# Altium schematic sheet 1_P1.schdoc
size 429 x 307 mm; Symbol: Drawing-Symbol_A4; Device: Drawing-Symbol_A4; @Project Name: grandPA2; @Page Count: 1; @Update Date: 2026-07-21; @Create Date: 2026-07-15; @Schematic Name: matrix; @Page No: 1; @Page Name: P1; Company: EasyEDA.com; Version: v0.2; Page Size: A4; @Create Time: 07:05:13; @Update Time: 17:13:13; Width: 1655; Height: 1170; Region Start: 1; X Region Count: 6; Y Region Count: 4; Blade Width: 10; Title Block Position: 3; @Board Name: matrix
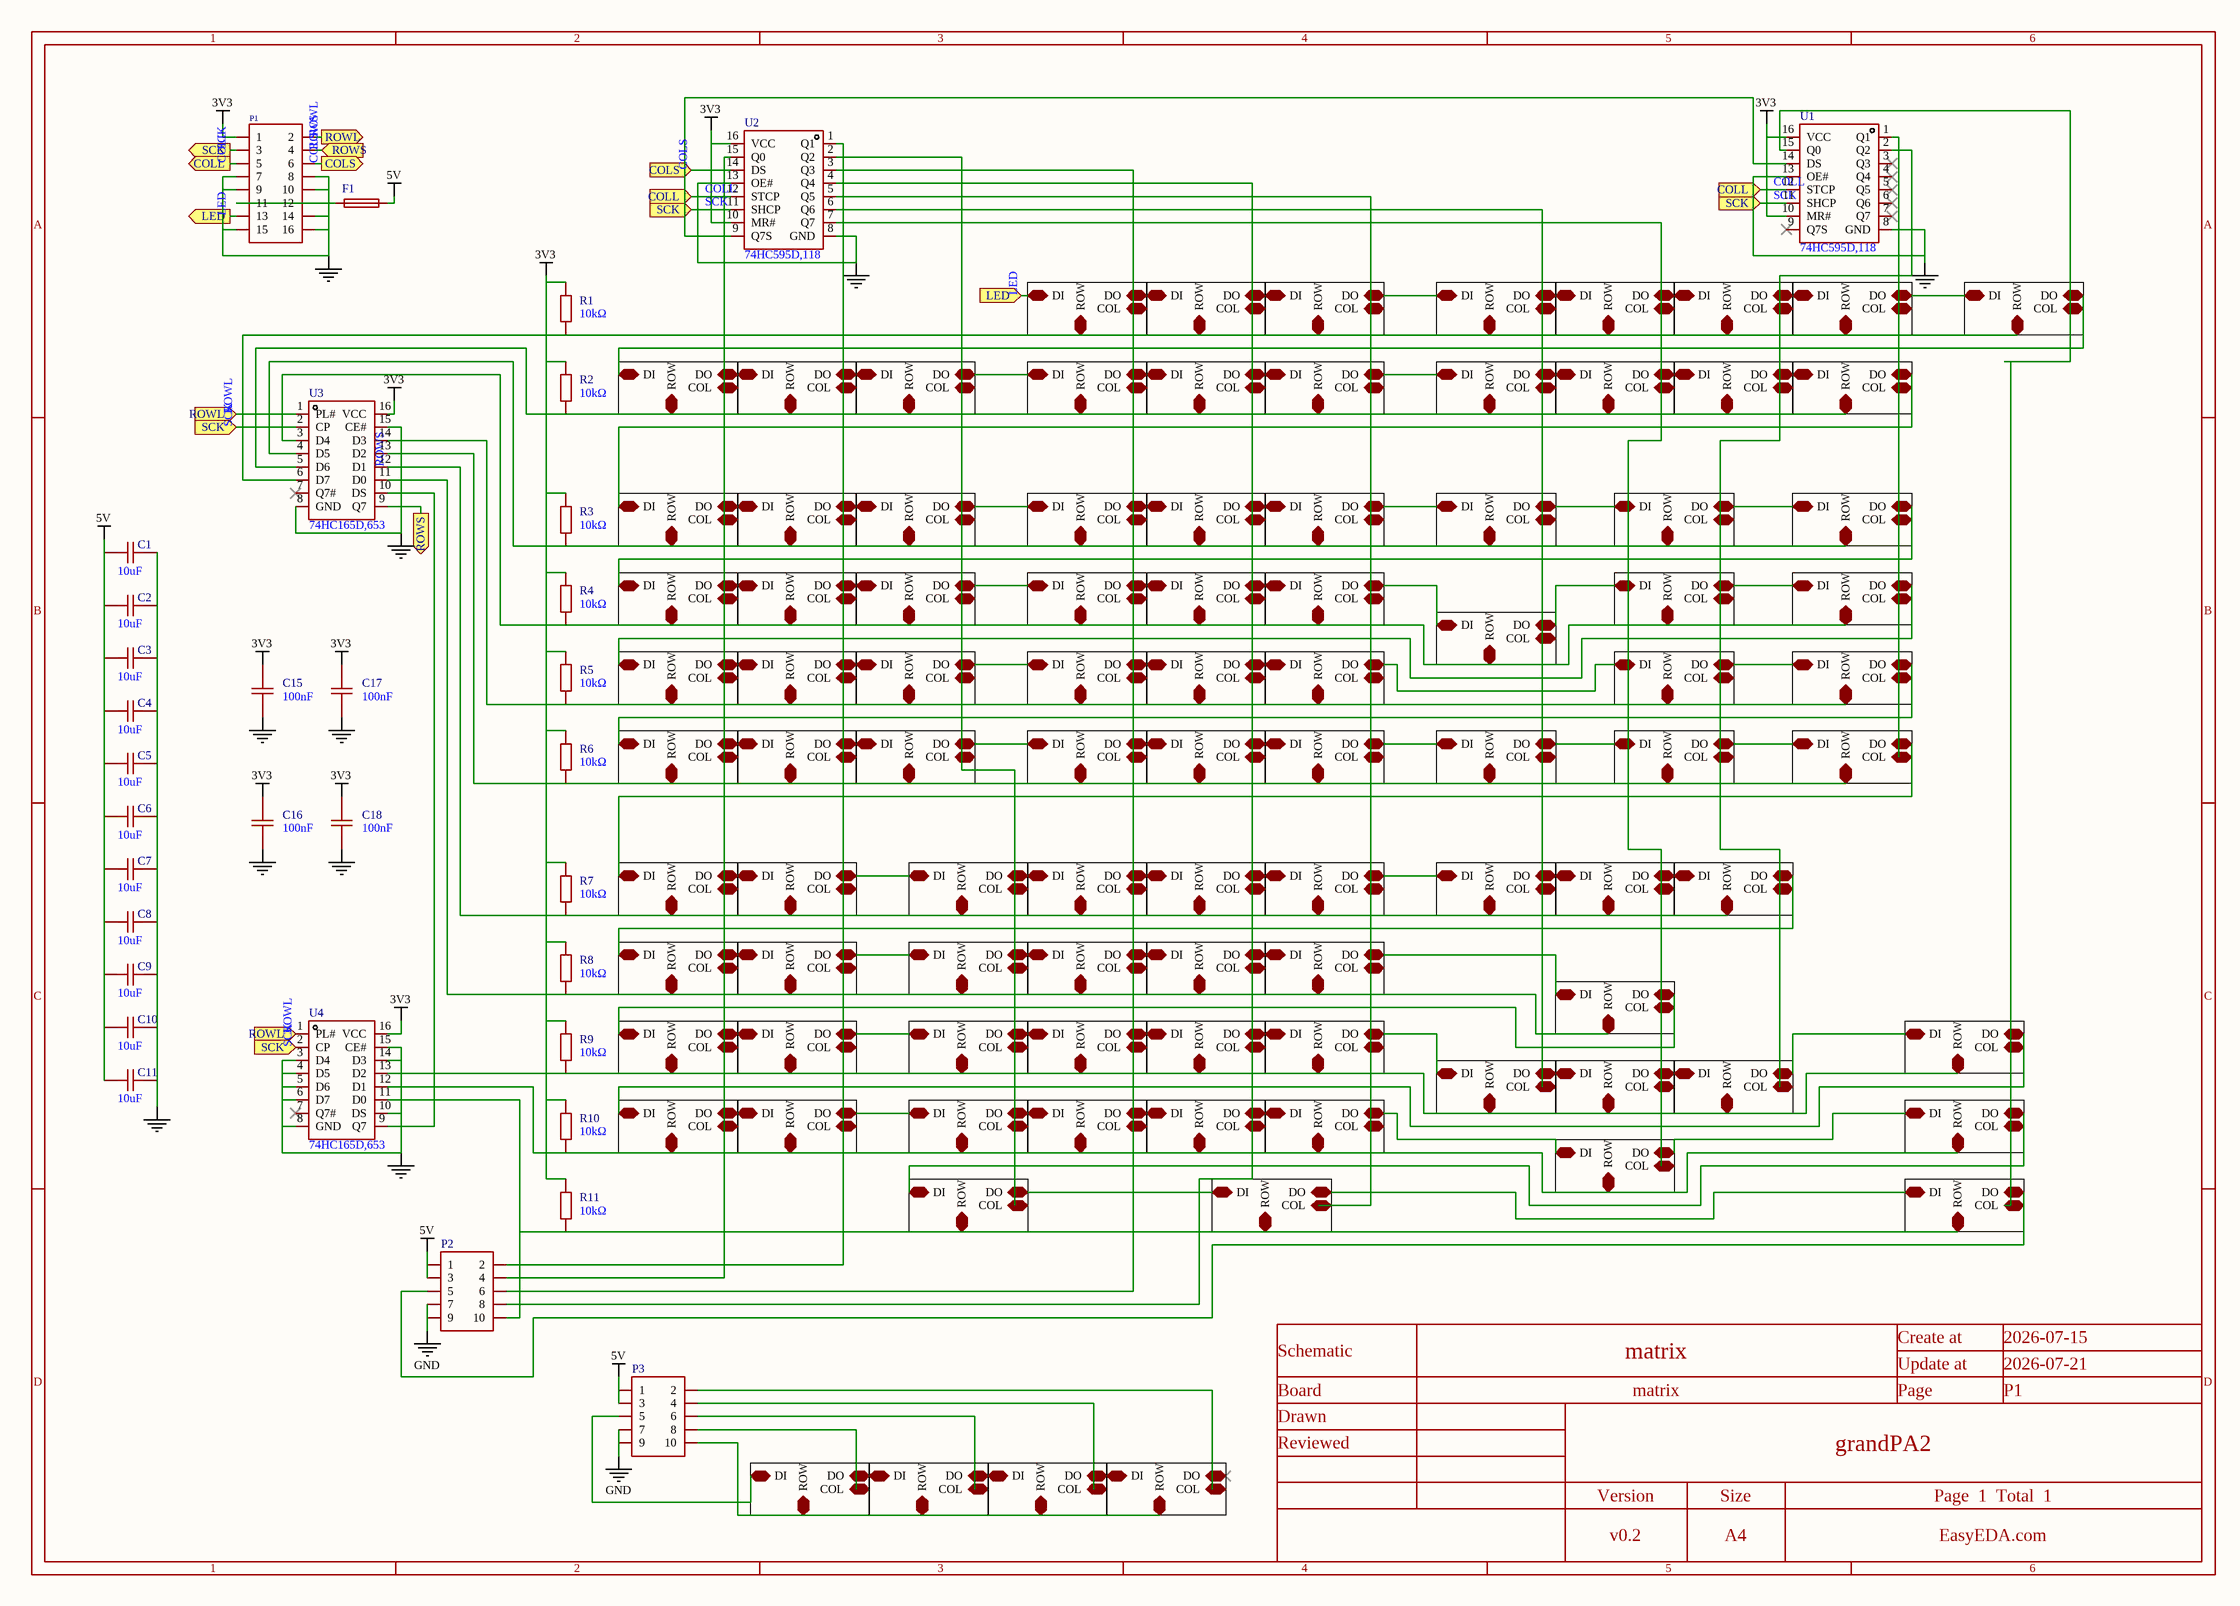
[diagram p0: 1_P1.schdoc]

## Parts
C1  10uF  [C0805]
C2  10uF  [C0805]
C3  10uF  [C0805]
C4  10uF  [C0805]
C5  10uF  [C0805]
C6  10uF  [C0805]
C7  10uF  [C0805]
C8  10uF  [C0805]
C9  10uF  [C0805]
C10  10uF  [C0805]
C11  10uF  [C0805]
C15  100nF  [C0402]
C16  100nF  [C0402]
C17  100nF  [C0402]
C18  100nF  [C0402]
F1  1812L150/24MR  [F1812]  (value not drawn)
P1  2.54-2*8P简牛  [IDC-TH_16P-P2.54_C3406]  (value not drawn)
P2  2.54-2*5P简牛  [IDC-TH_10P-P2.54_C5665]  (value not drawn)
P3  2.54-2*5P简牛  [IDC-TH_10P-P2.54_C5665]  (value not drawn)
R1  10kΩ  [R0402]
R2  10kΩ  [R0402]
R3  10kΩ  [R0402]
R4  10kΩ  [R0402]
R5  10kΩ  [R0402]
R6  10kΩ  [R0402]
R7  10kΩ  [R0402]
R8  10kΩ  [R0402]
R9  10kΩ  [R0402]
R10  10kΩ  [R0402]
R11  10kΩ  [R0402]
U1  74HC595D,118  [SOIC-16_L9.9-W3.9-P1.27-LS6.0-BL]
U2  74HC595D,118  [SOIC-16_L9.9-W3.9-P1.27-LS6.0-BL]
U3  74HC165D,653  [SOIC-16_L9.9-W3.9-P1.27-LS6.0-BL]
U4  74HC165D,653  [SOIC-16_L9.9-W3.9-P1.27-LS6.0-BL]

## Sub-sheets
CBB1 = 1_P1.schdoc: ROW, DI, COL, DO  | Symbol: Key; Device: Key; Relevance: []
CBB2 = 1_P1.schdoc: ROW, DI, COL, DO  | Symbol: Key; Device: Key; Relevance: []
CBB3 = 1_P1.schdoc: ROW, DI, COL, DO  | Symbol: Key; Device: Key; Relevance: []
CBB4 = 1_P1.schdoc: ROW, DI, COL, DO  | Symbol: Key; Device: Key; Relevance: []
CBB5 = 1_P1.schdoc: ROW, DI, COL, DO  | Symbol: Key; Device: Key; Relevance: []
CBB6 = 1_P1.schdoc: ROW, DI, COL, DO  | Symbol: Key; Device: Key; Relevance: []
CBB7 = 1_P1.schdoc: ROW, DI, COL, DO  | Symbol: Key; Device: Key; Relevance: []
CBB8 = 1_P1.schdoc: ROW, DI, COL, DO  | Symbol: Key; Device: Key; Relevance: []
CBB9 = 1_P1.schdoc: ROW, DI, COL, DO  | Symbol: Key; Device: Key; Relevance: []
CBB10 = 1_P1.schdoc: ROW, DI, COL, DO  | Symbol: Key; Device: Key; Relevance: []
CBB11 = 1_P1.schdoc: ROW, DI, COL, DO  | Symbol: Key; Device: Key; Relevance: []
CBB12 = 1_P1.schdoc: ROW, DI, COL, DO  | Symbol: Key; Device: Key; Relevance: []
CBB13 = 1_P1.schdoc: ROW, DI, COL, DO  | Symbol: Key; Device: Key; Relevance: []
CBB14 = 1_P1.schdoc: ROW, DI, COL, DO  | Symbol: Key; Device: Key; Relevance: []
CBB15 = 1_P1.schdoc: ROW, DI, COL, DO  | Symbol: Key; Device: Key; Relevance: []
CBB16 = 1_P1.schdoc: ROW, DI, COL, DO  | Symbol: Key; Device: Key; Relevance: []
CBB17 = 1_P1.schdoc: ROW, DI, COL, DO  | Symbol: Key; Device: Key; Relevance: []
CBB18 = 1_P1.schdoc: ROW, DI, COL, DO  | Symbol: Key; Device: Key; Relevance: []
CBB19 = 1_P1.schdoc: ROW, DI, COL, DO  | Symbol: Key; Device: Key; Relevance: []
CBB20 = 1_P1.schdoc: ROW, DI, COL, DO  | Symbol: Key; Device: Key; Relevance: []
CBB21 = 1_P1.schdoc: ROW, DI, COL, DO  | Symbol: Key; Device: Key; Relevance: []
CBB22 = 1_P1.schdoc: ROW, DI, COL, DO  | Symbol: Key; Device: Key; Relevance: []
CBB23 = 1_P1.schdoc: ROW, DI, COL, DO  | Symbol: Key; Device: Key; Relevance: []
CBB24 = 1_P1.schdoc: ROW, DI, COL, DO  | Symbol: Key; Device: Key; Relevance: []
CBB25 = 1_P1.schdoc: ROW, DI, COL, DO  | Symbol: Key; Device: Key; Relevance: []
CBB26 = 1_P1.schdoc: ROW, DI, COL, DO  | Symbol: Key; Device: Key; Relevance: []
CBB27 = 1_P1.schdoc: ROW, DI, COL, DO  | Symbol: Key; Device: Key; Relevance: []
CBB28 = 1_P1.schdoc: ROW, DI, COL, DO  | Symbol: Key; Device: Key; Relevance: []
CBB29 = 1_P1.schdoc: ROW, DI, COL, DO  | Symbol: Key; Device: Key; Relevance: []
CBB30 = 1_P1.schdoc: ROW, DI, COL, DO  | Symbol: Key; Device: Key; Relevance: []
CBB31 = 1_P1.schdoc: ROW, DI, COL, DO  | Symbol: Key; Device: Key; Relevance: []
CBB32 = 1_P1.schdoc: ROW, DI, COL, DO  | Symbol: Key; Device: Key; Relevance: []
CBB33 = 1_P1.schdoc: ROW, DI, COL, DO  | Symbol: Key; Device: Key; Relevance: []
CBB34 = 1_P1.schdoc: ROW, DI, COL, DO  | Symbol: Key; Device: Key; Relevance: []
CBB35 = 1_P1.schdoc: ROW, DI, COL, DO  | Symbol: Key; Device: Key; Relevance: []
CBB36 = 1_P1.schdoc: ROW, DI, COL, DO  | Symbol: Key; Device: Key; Relevance: []
CBB37 = 1_P1.schdoc: ROW, DI, COL, DO  | Symbol: Key; Device: Key; Relevance: []
CBB38 = 1_P1.schdoc: ROW, DI, COL, DO  | Symbol: Key; Device: Key; Relevance: []
CBB39 = 1_P1.schdoc: ROW, DI, COL, DO  | Symbol: Key; Device: Key; Relevance: []
CBB40 = 1_P1.schdoc: ROW, DI, COL, DO  | Symbol: Key; Device: Key; Relevance: []
CBB41 = 1_P1.schdoc: ROW, DI, COL, DO  | Symbol: Key; Device: Key; Relevance: []
CBB42 = 1_P1.schdoc: ROW, DI, COL, DO  | Symbol: Key; Device: Key; Relevance: []
CBB43 = 1_P1.schdoc: ROW, DI, COL, DO  | Symbol: Key; Device: Key; Relevance: []
CBB44 = 1_P1.schdoc: ROW, DI, COL, DO  | Symbol: Key; Device: Key; Relevance: []
CBB45 = 1_P1.schdoc: ROW, DI, COL, DO  | Symbol: Key; Device: Key; Relevance: []
CBB46 = 1_P1.schdoc: ROW, DI, COL, DO  | Symbol: Key; Device: Key; Relevance: []
CBB47 = 1_P1.schdoc: ROW, DI, COL, DO  | Symbol: Key; Device: Key; Relevance: []
CBB48 = 1_P1.schdoc: ROW, DI, COL, DO  | Symbol: Key; Device: Key; Relevance: []
CBB49 = 1_P1.schdoc: ROW, DI, COL, DO  | Symbol: Key; Device: Key; Relevance: []
CBB50 = 1_P1.schdoc: ROW, DI, COL, DO  | Symbol: Key; Device: Key; Relevance: []
CBB51 = 1_P1.schdoc: ROW, DI, COL, DO  | Symbol: Key; Device: Key; Relevance: []
CBB52 = 1_P1.schdoc: ROW, DI, COL, DO  | Symbol: Key; Device: Key; Relevance: []
CBB53 = 1_P1.schdoc: ROW, DI, COL, DO  | Symbol: Key; Device: Key; Relevance: []
CBB54 = 1_P1.schdoc: ROW, DI, COL, DO  | Symbol: Key; Device: Key; Relevance: []
CBB55 = 1_P1.schdoc: ROW, DI, COL, DO  | Symbol: Key; Device: Key; Relevance: []
CBB56 = 1_P1.schdoc: ROW, DI, COL, DO  | Symbol: Key; Device: Key; Relevance: []
CBB57 = 1_P1.schdoc: ROW, DI, COL, DO  | Symbol: Key; Device: Key; Relevance: []
CBB58 = 1_P1.schdoc: ROW, DI, COL, DO  | Symbol: Key; Device: Key; Relevance: []
CBB59 = 1_P1.schdoc: ROW, DI, COL, DO  | Symbol: Key; Device: Key; Relevance: []
CBB60 = 1_P1.schdoc: ROW, DI, COL, DO  | Symbol: Key; Device: Key; Relevance: []
CBB61 = 1_P1.schdoc: ROW, DI, COL, DO  | Symbol: Key; Device: Key; Relevance: []
CBB62 = 1_P1.schdoc: ROW, DI, COL, DO  | Symbol: Key; Device: Key; Relevance: []
CBB63 = 1_P1.schdoc: ROW, DI, COL, DO  | Symbol: Key; Device: Key; Relevance: []
CBB64 = 1_P1.schdoc: ROW, DI, COL, DO  | Symbol: Key; Device: Key; Relevance: []
CBB65 = 1_P1.schdoc: ROW, DI, COL, DO  | Symbol: Key; Device: Key; Relevance: []
CBB66 = 1_P1.schdoc: ROW, DI, COL, DO  | Symbol: Key; Device: Key; Relevance: []
CBB67 = 1_P1.schdoc: ROW, DI, COL, DO  | Symbol: Key; Device: Key; Relevance: []
CBB68 = 1_P1.schdoc: ROW, DI, COL, DO  | Symbol: Key; Device: Key; Relevance: []
CBB69 = 1_P1.schdoc: ROW, DI, COL, DO  | Symbol: Key; Device: Key; Relevance: []
CBB70 = 1_P1.schdoc: ROW, DI, COL, DO  | Symbol: Key; Device: Key; Relevance: []
CBB71 = 1_P1.schdoc: ROW, DI, COL, DO  | Symbol: Key; Device: Key; Relevance: []
CBB72 = 1_P1.schdoc: ROW, DI, COL, DO  | Symbol: Key; Device: Key; Relevance: []
CBB73 = 1_P1.schdoc: ROW, DI, COL, DO  | Symbol: Key; Device: Key; Relevance: []
CBB74 = 1_P1.schdoc: ROW, DI, COL, DO  | Symbol: Key; Device: Key; Relevance: []
CBB75 = 1_P1.schdoc: ROW, DI, COL, DO  | Symbol: Key; Device: Key; Relevance: []
CBB76 = 1_P1.schdoc: ROW, DI, COL, DO  | Symbol: Key; Device: Key; Relevance: []
CBB77 = 1_P1.schdoc: ROW, DI, COL, DO  | Symbol: Key; Device: Key; Relevance: []
CBB78 = 1_P1.schdoc: ROW, DI, COL, DO  | Symbol: Key; Device: Key; Relevance: []
CBB79 = 1_P1.schdoc: ROW, DI, COL, DO  | Symbol: Key; Device: Key; Relevance: []
CBB80 = 1_P1.schdoc: ROW, DI, COL, DO  | Symbol: Key; Device: Key; Relevance: []
CBB81 = 1_P1.schdoc: ROW, DI, COL, DO  | Symbol: Key; Device: Key; Relevance: []
CBB82 = 1_P1.schdoc: ROW, DI, COL, DO  | Symbol: Key; Device: Key; Relevance: []
CBB83 = 1_P1.schdoc: ROW, DI, COL, DO  | Symbol: Key; Device: Key; Relevance: []
CBB84 = 1_P1.schdoc: ROW, DI, COL, DO  | Symbol: Key; Device: Key; Relevance: []
CBB85 = 1_P1.schdoc: ROW, DI, COL, DO  | Symbol: Key; Device: Key; Relevance: []
CBB86 = 1_P1.schdoc: ROW, DI, COL, DO  | Symbol: Key; Device: Key; Relevance: []
CBB87 = 1_P1.schdoc: ROW, DI, COL, DO  | Symbol: Key; Device: Key; Relevance: []
KEY1 = 1_P1.schdoc: ROW, DI, COL, DO  | Symbol: Key; Device: Key; Relevance: []
KEY2 = 1_P1.schdoc: ROW, DI, COL, DO  | Symbol: Key; Device: Key; Relevance: []
KEY3 = 1_P1.schdoc: ROW, DI, COL, DO  | Symbol: Key; Device: Key; Relevance: []
KEY4 = 1_P1.schdoc: ROW, DI, COL, DO  | Symbol: Key; Device: Key; Relevance: []
KEY5 = 1_P1.schdoc: ROW, DI, COL, DO  | Symbol: Key; Device: Key; Relevance: []
KEY6 = 1_P1.schdoc: ROW, DI, COL, DO  | Symbol: Key; Device: Key; Relevance: []
KEY7 = 1_P1.schdoc: ROW, DI, COL, DO  | Symbol: Key; Device: Key; Relevance: []

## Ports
COLL (in), COLL (out), COLS (in), COLS (out), LED (in), LED (out), ROWL (in), ROWL (out), ROWS (in), ROWS (out), SCK (in), SCK (out)

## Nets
3V3: C15.2 C16.2 C17.2 C18.2 P1.1 R1.2 R2.2 R3.2 R4.2 R5.2 R6.2 R7.2 R8.2 R9.2 R10.2 R11.2 U1.10(MR#) U1.16(VCC) U2.10(MR#) U2.16(VCC) U3.16(VCC) U4.16(VCC)
5V: C1.2 C2.2 C3.1 C4.2 C5.2 C6.2 C7.2 C8.2 C9.2 C10.2 C11.2 F1.2 P2.1 P2.3 P3.1 P3.3
GND: C1.1 C2.1 C3.2 C4.1 C5.1 C6.1 C7.1 C8.1 C9.1 C10.1 C11.1 C15.1 C16.1 C17.1 C18.1 P1.7 P1.8 P1.9 P1.10 P1.14 P1.15 P1.16 P2.7 P2.9 P3.7 P3.9 U1.8(GND) U1.13(OE#) U2.8(GND) U2.13(OE#) U3.8(GND) U3.15(CE#) U4.3(D4) U4.4(D5) U4.5(D6) U4.6(D7) U4.8(GND) U4.10(DS) U4.14(D3) U4.15(CE#)
COLL: P1.5 U1.12(STCP) U2.12(STCP) ; port COLL
COLS: P1.6 U2.14(DS) ; port COLS
LED: P1.13 ; port LED, sheet KEY7/DI
ROWL: P1.2 U3.1(PL#) U4.1(PL#) ; port ROWL
ROWS: P1.4 R7.1 U3.9(Q7) U3.12(D1) ; port ROWS, sheet CBB36/ROW, sheet CBB37/ROW, sheet CBB38/ROW, sheet CBB39/ROW, sheet CBB40/ROW, sheet CBB41/ROW, sheet CBB71/ROW, sheet CBB72/ROW, sheet CBB73/ROW
SCK: P1.3 U1.11(SHCP) U2.11(SHCP) U3.2(CP) U4.2(CP) ; port SCK
NetF1_1: F1.1 P1.11 P1.12
NetP2_2: P2.2 U2.1(Q1)
NetP2_4: P2.4 U2.15(Q0)
NetP2_5: P2.5 ; sheet CBB87/COL, sheet CBB87/DO
NetP2_6: P2.6 U2.3(Q3)
NetP2_8: P2.8 U2.4(Q4)
NetP2_10: P2.10 R11.1 U4.11(D0) ; sheet CBB79/ROW, sheet CBB84/ROW, sheet CBB87/ROW
NetP3_5: P3.5 ; sheet CBB80/DI
NetP3_10: P3.10 ; sheet CBB80/ROW, sheet CBB81/ROW, sheet CBB82/ROW, sheet CBB83/ROW
NetR1_1: R1.1 U3.6(D7) ; sheet CBB1/ROW, sheet KEY1/ROW, sheet KEY2/ROW, sheet KEY3/ROW, sheet KEY4/ROW, sheet KEY5/ROW, sheet KEY6/ROW, sheet KEY7/ROW
NetR2_1: R2.1 U3.5(D6) ; sheet CBB2/ROW, sheet CBB3/ROW, sheet CBB4/ROW, sheet CBB5/ROW, sheet CBB6/ROW, sheet CBB7/ROW, sheet CBB8/ROW, sheet CBB9/ROW, sheet CBB10/ROW, sheet CBB11/ROW
NetR3_1: R3.1 U3.4(D5) ; sheet CBB12/ROW, sheet CBB13/ROW, sheet CBB14/ROW, sheet CBB15/ROW, sheet CBB16/ROW, sheet CBB17/ROW, sheet CBB60/ROW, sheet CBB65/ROW, sheet CBB68/ROW
NetR4_1: R4.1 U3.3(D4) ; sheet CBB18/ROW, sheet CBB19/ROW, sheet CBB20/ROW, sheet CBB21/ROW, sheet CBB22/ROW, sheet CBB23/ROW, sheet CBB61/ROW, sheet CBB64/ROW, sheet CBB69/ROW
NetR5_1: R5.1 U3.14(D3) ; sheet CBB24/ROW, sheet CBB25/ROW, sheet CBB26/ROW, sheet CBB27/ROW, sheet CBB28/ROW, sheet CBB29/ROW, sheet CBB62/ROW, sheet CBB67/ROW
NetR6_1: R6.1 U3.13(D2) ; sheet CBB30/ROW, sheet CBB31/ROW, sheet CBB32/ROW, sheet CBB33/ROW, sheet CBB34/ROW, sheet CBB35/ROW, sheet CBB63/ROW, sheet CBB66/ROW, sheet CBB70/ROW
NetR8_1: R8.1 U3.11(D0) ; sheet CBB42/ROW, sheet CBB43/ROW, sheet CBB44/ROW, sheet CBB45/ROW, sheet CBB46/ROW, sheet CBB47/ROW, sheet CBB77/ROW
NetR9_1: R9.1 U4.13(D2) ; sheet CBB48/ROW, sheet CBB49/ROW, sheet CBB50/ROW, sheet CBB51/ROW, sheet CBB52/ROW, sheet CBB53/ROW, sheet CBB74/ROW, sheet CBB75/ROW, sheet CBB76/ROW, sheet CBB86/ROW
NetR10_1: R10.1 U4.12(D1) ; sheet CBB54/ROW, sheet CBB55/ROW, sheet CBB56/ROW, sheet CBB57/ROW, sheet CBB58/ROW, sheet CBB59/ROW, sheet CBB78/ROW, sheet CBB85/ROW
NetU1_14: U1.14(DS) U2.9(Q7S)
NetU2_5: U2.5(Q5) ; sheet CBB84/COL
NetU3_10: U3.10(DS) U4.9(Q7)
(unnamed): sheet CBB1/DI, sheet KEY1/DO
(unnamed): sheet CBB1/COL, sheet CBB1/DO, sheet CBB11/DI  [a separate net that carries the same name]
(unnamed): sheet KEY1/DI, sheet KEY2/DO  [a separate net that carries the same name]
(unnamed): sheet CBB2/DI, sheet CBB3/DO  [a separate net that carries the same name]
(unnamed): sheet CBB2/COL, sheet CBB2/DO, sheet CBB17/DI  [a separate net that carries the same name]
(unnamed): sheet KEY2/DI, sheet KEY3/DO  [a separate net that carries the same name]
(unnamed): sheet CBB3/DI, sheet CBB4/DO  [a separate net that carries the same name]
(unnamed): sheet KEY3/DI, sheet KEY4/DO  [a separate net that carries the same name]
(unnamed): sheet CBB4/DI, sheet CBB5/DO  [a separate net that carries the same name]
(unnamed): sheet KEY4/DI, sheet KEY5/DO  [a separate net that carries the same name]
(unnamed): sheet CBB5/DI, sheet CBB6/DO  [a separate net that carries the same name]
(unnamed): sheet KEY5/DI, sheet KEY6/DO  [a separate net that carries the same name]
(unnamed): sheet CBB6/DI, sheet CBB7/DO  [a separate net that carries the same name]
(unnamed): sheet KEY6/DI, sheet KEY7/DO  [a separate net that carries the same name]
(unnamed): sheet CBB7/DI, sheet CBB8/DO  [a separate net that carries the same name]
(unnamed): sheet CBB8/DI, sheet CBB9/DO  [a separate net that carries the same name]
(unnamed): sheet CBB9/DI, sheet CBB10/DO  [a separate net that carries the same name]
(unnamed): sheet CBB10/DI, sheet CBB11/DO  [a separate net that carries the same name]
(unnamed): sheet CBB12/DI, sheet CBB13/DO  [a separate net that carries the same name]
(unnamed): sheet CBB12/DO, sheet CBB68/DI  [a separate net that carries the same name]
(unnamed): sheet CBB13/DI, sheet CBB14/DO  [a separate net that carries the same name]
(unnamed): sheet CBB14/DI, sheet CBB15/DO  [a separate net that carries the same name]
(unnamed): sheet CBB15/DI, sheet CBB16/DO  [a separate net that carries the same name]
(unnamed): sheet CBB16/DI, sheet CBB17/DO  [a separate net that carries the same name]
(unnamed): sheet CBB18/DI, sheet CBB19/DO  [a separate net that carries the same name]
(unnamed): sheet CBB18/DO, sheet CBB69/DI  [a separate net that carries the same name]
(unnamed): sheet CBB19/DI, sheet CBB20/DO  [a separate net that carries the same name]
(unnamed): sheet CBB20/DI, sheet CBB21/DO  [a separate net that carries the same name]
(unnamed): sheet CBB21/DI, sheet CBB22/DO  [a separate net that carries the same name]
(unnamed): sheet CBB22/DI, sheet CBB23/DO  [a separate net that carries the same name]
(unnamed): sheet CBB23/DI, sheet CBB60/COL, sheet CBB60/DO  [a separate net that carries the same name]
(unnamed): sheet CBB24/DI, sheet CBB25/DO  [a separate net that carries the same name]
(unnamed): sheet CBB24/DO, sheet CBB67/DI  [a separate net that carries the same name]
(unnamed): sheet CBB25/DI, sheet CBB26/DO  [a separate net that carries the same name]
(unnamed): sheet CBB26/DI, sheet CBB27/DO  [a separate net that carries the same name]
(unnamed): sheet CBB27/DI, sheet CBB28/DO  [a separate net that carries the same name]
(unnamed): sheet CBB28/DI, sheet CBB29/DO  [a separate net that carries the same name]
(unnamed): sheet CBB29/DI, sheet CBB61/COL, sheet CBB61/DO  [a separate net that carries the same name]
(unnamed): sheet CBB30/DI, sheet CBB31/DO  [a separate net that carries the same name]
(unnamed): sheet CBB30/DO, sheet CBB70/DI  [a separate net that carries the same name]
(unnamed): sheet CBB31/DI, sheet CBB32/DO  [a separate net that carries the same name]
(unnamed): sheet CBB32/DI, sheet CBB33/DO  [a separate net that carries the same name]
(unnamed): sheet CBB33/DI, sheet CBB34/DO  [a separate net that carries the same name]
(unnamed): sheet CBB34/DI, sheet CBB35/DO  [a separate net that carries the same name]
(unnamed): sheet CBB35/DI, sheet CBB62/COL, sheet CBB62/DO  [a separate net that carries the same name]
(unnamed): sheet CBB36/DI, sheet CBB37/DO  [a separate net that carries the same name]
(unnamed): sheet CBB36/DO, sheet CBB71/DI  [a separate net that carries the same name]
(unnamed): sheet CBB37/DI, sheet CBB38/DO  [a separate net that carries the same name]
(unnamed): sheet CBB38/DI, sheet CBB39/DO  [a separate net that carries the same name]
(unnamed): sheet CBB39/DI, sheet CBB40/DO  [a separate net that carries the same name]
(unnamed): sheet CBB40/DI, sheet CBB41/DO  [a separate net that carries the same name]
(unnamed): sheet CBB41/DI, sheet CBB63/COL, sheet CBB63/DO  [a separate net that carries the same name]
(unnamed): sheet CBB42/DI, sheet CBB43/DO  [a separate net that carries the same name]
(unnamed): sheet CBB42/DO, sheet CBB77/DI  [a separate net that carries the same name]
(unnamed): sheet CBB43/DI, sheet CBB44/DO  [a separate net that carries the same name]
(unnamed): sheet CBB44/DI, sheet CBB45/DO  [a separate net that carries the same name]
(unnamed): sheet CBB45/DI, sheet CBB46/DO  [a separate net that carries the same name]
(unnamed): sheet CBB46/DI, sheet CBB47/DO  [a separate net that carries the same name]
(unnamed): sheet CBB47/DI, sheet CBB73/COL, sheet CBB73/DO  [a separate net that carries the same name]
(unnamed): sheet CBB48/DI, sheet CBB49/DO  [a separate net that carries the same name]
(unnamed): sheet CBB48/DO, sheet CBB74/DI  [a separate net that carries the same name]
(unnamed): sheet CBB49/DI, sheet CBB50/DO  [a separate net that carries the same name]
(unnamed): sheet CBB50/DI, sheet CBB51/DO  [a separate net that carries the same name]
(unnamed): sheet CBB51/DI, sheet CBB52/DO  [a separate net that carries the same name]
(unnamed): sheet CBB52/DI, sheet CBB53/DO  [a separate net that carries the same name]
(unnamed): sheet CBB53/DI, sheet CBB77/COL, sheet CBB77/DO  [a separate net that carries the same name]
(unnamed): sheet CBB54/DI, sheet CBB55/DO  [a separate net that carries the same name]
(unnamed): sheet CBB54/DO, sheet CBB78/DI  [a separate net that carries the same name]
(unnamed): sheet CBB55/DI, sheet CBB56/DO  [a separate net that carries the same name]
(unnamed): sheet CBB56/DI, sheet CBB57/DO  [a separate net that carries the same name]
(unnamed): sheet CBB57/DI, sheet CBB58/DO  [a separate net that carries the same name]
(unnamed): sheet CBB58/DI, sheet CBB59/DO  [a separate net that carries the same name]
(unnamed): sheet CBB59/DI, sheet CBB86/COL, sheet CBB86/DO  [a separate net that carries the same name]
(unnamed): sheet CBB60/DI, sheet CBB65/DO  [a separate net that carries the same name]
(unnamed): sheet CBB61/DI, sheet CBB64/DO  [a separate net that carries the same name]
(unnamed): sheet CBB62/DI, sheet CBB67/DO  [a separate net that carries the same name]
(unnamed): sheet CBB63/DI, sheet CBB66/DO  [a separate net that carries the same name]
(unnamed): sheet CBB65/DI, sheet CBB68/DO  [a separate net that carries the same name]
(unnamed): sheet CBB64/DI, sheet CBB69/DO  [a separate net that carries the same name]
(unnamed): sheet CBB66/DI, sheet CBB70/DO  [a separate net that carries the same name]
(unnamed): sheet CBB71/DO, sheet CBB72/DI  [a separate net that carries the same name]
(unnamed): sheet CBB72/DO, sheet CBB73/DI  [a separate net that carries the same name]
(unnamed): sheet CBB74/DO, sheet CBB75/DI  [a separate net that carries the same name]
(unnamed): sheet CBB75/DO, sheet CBB76/DI  [a separate net that carries the same name]
(unnamed): sheet CBB76/DO, sheet CBB86/DI  [a separate net that carries the same name]
(unnamed): sheet CBB78/DO, sheet CBB85/DI  [a separate net that carries the same name]
(unnamed): sheet CBB79/DI, sheet CBB85/COL, sheet CBB85/DO  [a separate net that carries the same name]
(unnamed): sheet CBB79/DO, sheet CBB84/DI  [a separate net that carries the same name]
(unnamed): sheet CBB80/DO, sheet CBB81/DI  [a separate net that carries the same name]
(unnamed): sheet CBB81/DO, sheet CBB82/DI  [a separate net that carries the same name]
(unnamed): sheet CBB82/DO, sheet CBB83/DI  [a separate net that carries the same name]
(unnamed): sheet CBB84/DO, sheet CBB87/DI  [a separate net that carries the same name]

Not connected (* = marked no-connect by the designer): P3 2 4 6 8; U1 1(Q1) 2(Q2) 3(Q3)* 4(Q4)* 5(Q5)* 6(Q6)* 7(Q7)* 9(Q7S)* 15(Q0); U2 2(Q2) 6(Q6) 7(Q7); U3 7(Q7#)*; U4 7(Q7#)*

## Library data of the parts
C1-C11 = CL21A106KAYNNNE_C15850: Manufacturer: SAMSUNG(三星); Add into BOM: yes; Tolerance: ±10%; Voltage Rating: 25V; Temperature Coefficient: X5R
C15-C18 = CL05B104KO5NNNC: Manufacturer: SAMSUNG(三星); Add into BOM: yes; Tolerance: ±10%; Voltage Rating: 16V; Temperature Coefficient: X7R
F1 = 1812L150/24MR: Manufacturer: Littelfuse(美国力特); Add into BOM: yes; Voltage - Max: 24V; Current - Max: 20A; Hold Current: 1.5A; Trip Current: 3A; Power Dissipation: 800mW; Resistance - Initial (Ri) (Min): 40mΩ; Resistance - Post Trip (R1) (Max): 120mΩ; Time to Trip(Max): 1.5s
P1 = 2.54-2*8P简牛: Manufacturer: BOOMELE(博穆精密); Symbol: HDR-IDC-2.54-2X8P; Add into BOM: yes; Connector Type: IDC Header; Pitch: 2.54mm; Number of Positions or Pins: 2x8P; Current Rating: 1A; Holder Type: Through Hole; Number of PINs Per Row: 8
P2 P3 = 2.54-2*5P简牛: Manufacturer: BOOMELE(博穆精密); Symbol: HDR-IDC-2.54-2X5P; Add into BOM: yes; Connector Type: IDC Header; Pitch: 2.54mm; Number of Positions or Pins: 2x5P; Current Rating: 1A; Holder Type: Through Hole; Number of PINs Per Row: 5
R1-R11 = 0402WGF1002TCE: Manufacturer: UNI-ROYAL(厚声); Add into BOM: yes; Tolerance: ±1%; Power(Watts): 62.5mW; Voltage-Supply(Max): 50V; Temperature Coefficient: ±100ppm/℃
U1 U2 = 74HC595D,118: Manufacturer: Nexperia(安世); Add into BOM: yes; Function: Serial-to-Serial or Parallel; Voltage - Supply: 2V~6V; Clock Frequency: 100MHz; Number of Elements: 1; Number of Bits per Element: 8; Output Type: Tri-State; Propagation Delay: 19ns@4.5V,50pF
U3 U4 = 74HC165D,653: Manufacturer: Nexperia(安世); Add into BOM: yes; Function: Parallel or Serial to Serial; Voltage - Supply: 2V~6V; Clock Frequency: 35MHz; Number of Elements: 1; Number of Bits per Element: 8; Output Type: Complementary type; Pd - Power Dissipation: 500mW; Propagation Delay: 28ns@6V,50pF; Output Current: 25mA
